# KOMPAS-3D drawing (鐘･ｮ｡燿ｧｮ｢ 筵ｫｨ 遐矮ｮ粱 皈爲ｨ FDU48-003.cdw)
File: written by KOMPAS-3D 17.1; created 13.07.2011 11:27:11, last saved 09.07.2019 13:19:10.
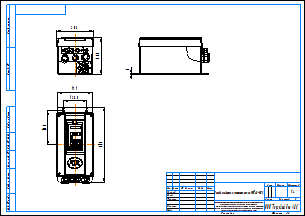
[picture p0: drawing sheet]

Title block, sheet 1: name: Преобразователи частоты серии FDU48-003; scale: 1:4; sheets: 1; sheet format: A3; stored path: \\adlc.lan\data\АДЛ_ПКД\3D-модели\Поставщики\Оборудование Emotron\Преобразователи частоты\Серия FDU 2.0\KOMPAS 2D\Преобразователи частоты серии FDU48-003.cdw

Views: Спереди 1
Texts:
  Рама для чертежей
  Лит-Масса-Масштаб
  Материал-Предприятие
  Масштаб
  Изм.
  Лист
  № докум.
  Подп.
  Дата
  Лит.
  Разраб.
  Пров.
  Т.контр.
  Листов
  Внимание! Данный продукт является объектом авторского права ООО «Торговый Дом АДЛ».
  Запрещается изменение, копирование, распространение
  (в том числе путем копирования на другие сайты и ресурсы в Интернете)
  или любое иное использование информации и объектов без предварительного
  согласия правообладателя (ООО «Торговый Дом АДЛ»).
  Н.контр.
  Утв.
  ООО "Торговый дом АДЛ"
  Изменение
  Номер документа
  Подпись
  Обозначение документа
  Наименование изделия
  Масса изделия по ГОСТ 2.109-73
  Порядковый номер листа
  Общее количество листов в документе
  Характер работы, выполненной лицом, подписавшим документ
  Наименование или индекс предприятия, выпускающего документ
  Инв. № подл.
  Подп. и дата
  Взам. инв. №
  Инв. № дубл.
  Инвентарный номер подлинника по ГОСТ 2.501-68
  Подпись принявшего подлинник в отдел технической документации
  Инвентарный номер подлинника, взамен которого выпущен данный подлинник
  Инвентарный номер дубликата по ГОСТ 2.502-68
  Подпись принявшего дубликат в отдел технической документации
  Справ. №
  Перв. примен.
  Обозначение документа, взамен или на основании которого выпущен данный документ
  Обозначение документа, в котором впервые записан данный документ
  Подпись лица, копировавшего чертеж
  Обозначение формата листа
  !Рама для чертежа
Dimensions and other numbers on the sheet: 203; 416; 2; 191; 128,5; 188; 1:4; 1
